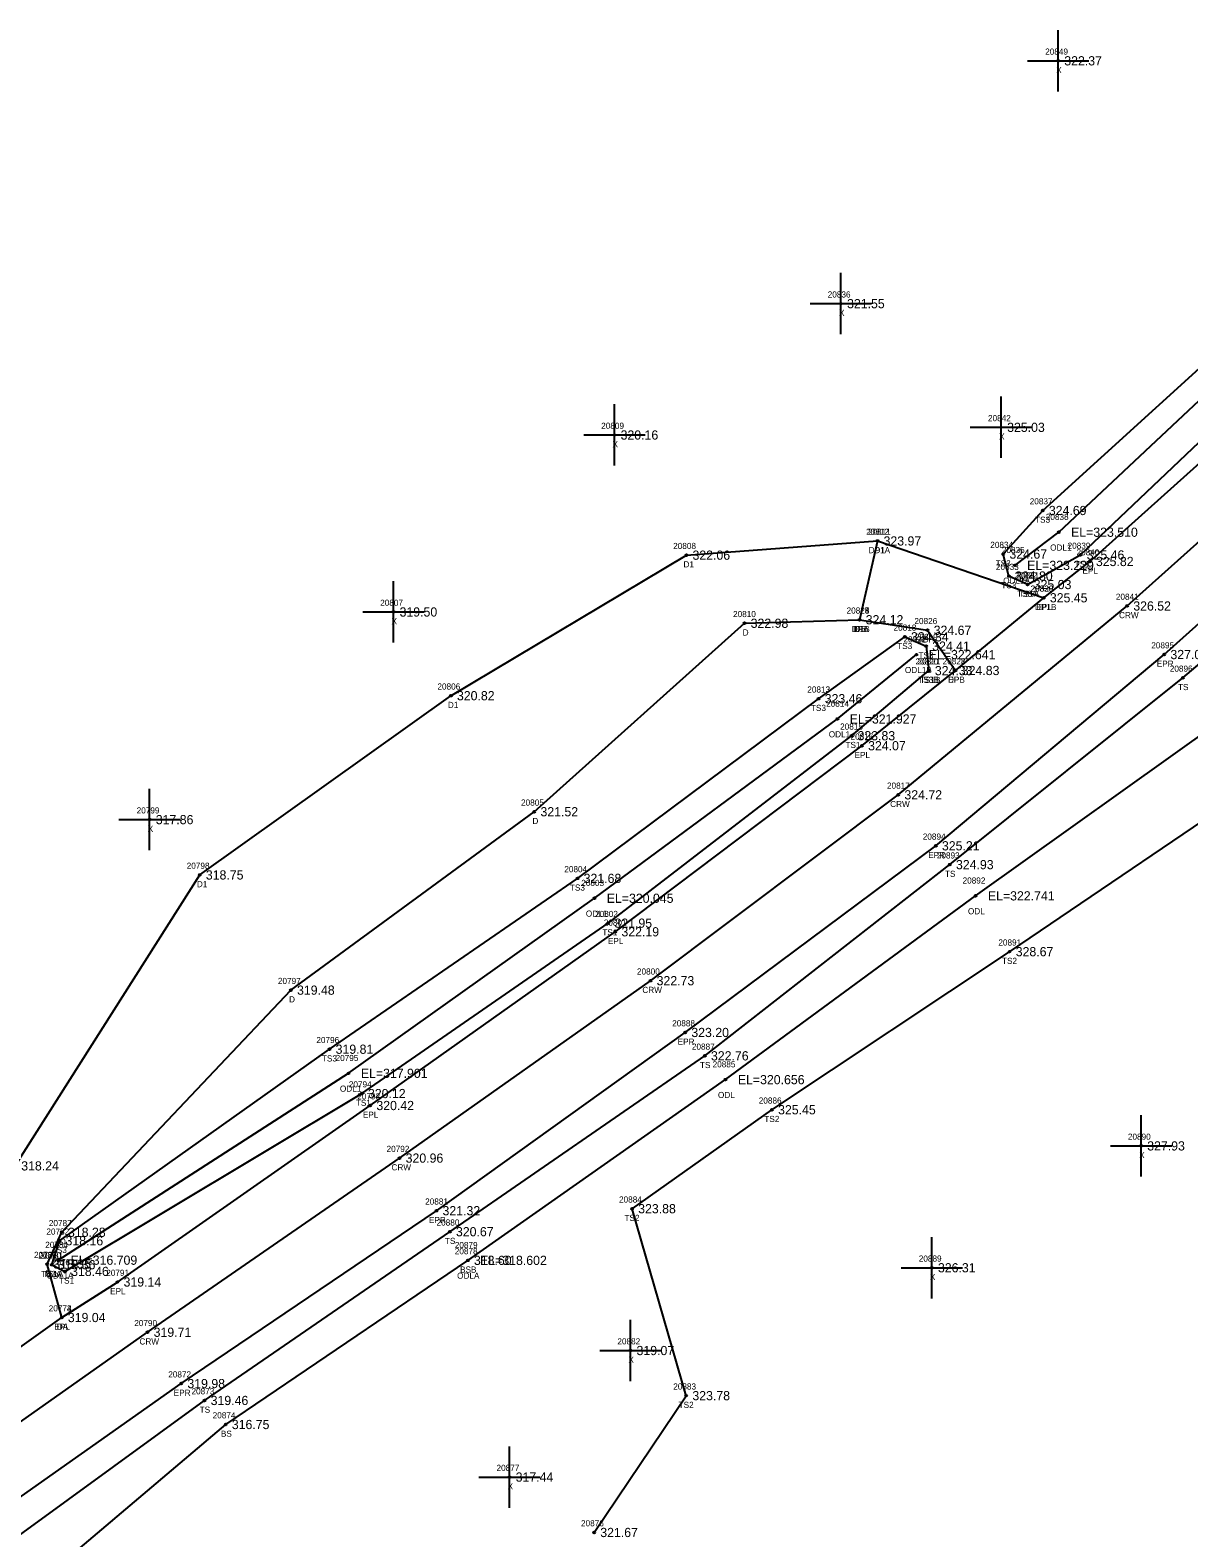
# Model space of a CAD drawing. Extents: x 1865771 to 1866867, y 910387 to 913581.
# Drawn here: x 1866485.5 to 1866674.4, y 913298.4 to 913544.2 of the extents above; entities that cross this region are included whole.
import ezdxf

# ---------------------------------------------------------------- set-up
doc = ezdxf.new("R2010")
doc.units = 0
for name, color, linetype in [('RD_DTM_BkLn1', 7, 'Continuous'), ('RD_DTM_BkLn2', 7, 'Continuous'), ('RD_DTM_BkLn_txCode', 7, 'Continuous'), ('RD_EX_Driveway', 7, 'Continuous'), ('RD_EX_Driveway_txCode', 7, 'Continuous'), ('RD_EX_H2O', 7, 'Continuous'), ('RD_EX_H2O_txCode', 7, 'Continuous'), ('RD_EX_Misc', 7, 'Continuous'), ('RD_EX_Misc_txCode', 7, 'Continuous'), ('RD_EX_Road', 7, 'Continuous'), ('RD_EX_Road_txCode', 7, 'Continuous'), ('RD_EX_TX_Driveway_ELEV', 7, 'Continuous'), ('RD_EX_TX_H2O_ELEV', 7, 'Continuous'), ('RD_EX_TX_Misc_ELEV', 7, 'Continuous'), ('RD_EX_TX_Road_ELEV', 7, 'Continuous'), ('RD_HC_Survey_ELEV', 7, 'Continuous'), ('RD_HC_Survey_txCode', 7, 'Continuous'), ('RD_SMD_Locator', 7, 'Continuous')]:
    doc.layers.add(name, color=color, linetype=linetype)

msp = doc.modelspace()

# ---------------------------------------------------------------- linework, layer by layer
at = {"layer": 'RD_DTM_BkLn1'}
msp.add_lwpolyline([(1866198.19, 913076.43), (1866231.43, 913114.18), (1866266.39, 913149.89), (1866303.96, 913183.9), (1866342.32, 913215.01), (1866422.98, 913274.26), (1866504.67, 913331.92), (1866545.74, 913360.31), (1866586.64, 913389.23), (1866627.03, 913419.53), (1866664.33, 913450.32), (1866701.01, 913483.14), (1866738.23, 913519.69)], dxfattribs=at)
at = {"layer": 'RD_DTM_BkLn2'}
for points in [[(1866648.11, 913453.81), (1866645.06, 913455.2), (1866644.14, 913458.78), (1866650.57, 913465.88), (1866688, 913499.92), (1866720.64, 913534.32)], [(1866648.11, 913453.81), (1866656.74, 913458.64), (1866693.26, 913493.4), (1866726.81, 913527.33)], [(1866443.26, 913211.06), (1866417.42, 913242.5), (1866419.02, 913252.7), (1866432.66, 913261.59), (1866513.96, 913320.8), (1866553.94, 913348.31), (1866595.5, 913376.98), (1866635.43, 913408.15), (1866673.42, 913438.6), (1866712.76, 913471.89), (1866747.8, 913506.8)], [(1866577.46, 913299.28), (1866592.47, 913321.58), (1866583.64, 913352.06), (1866606.44, 913368.19), (1866645.17, 913393.96), (1866688.43, 913423.29), (1866720.88, 913447.65), (1866761.04, 913493.25)], [(1866489.05, 913342.93), (1866490.31, 913346.83), (1866534.33, 913378.06), (1866574.75, 913405.91), (1866614.04, 913435.2), (1866628.1, 913445.29), (1866631.56, 913443.77), (1866631.99, 913439.78)], [(1866489.05, 913342.93), (1866491.22, 913341.84), (1866539.6, 913370.83), (1866579.77, 913398.61), (1866619.38, 913429.16), (1866631.99, 913439.78)], [(1866443.26, 913211.06), (1866430.21, 913243.04), (1866517.41, 913316.88), (1866556.87, 913343.64)]]:
    msp.add_lwpolyline(points, dxfattribs=at)
at = {"layer": 'RD_EX_Driveway'}
msp.add_line((1866623.63, 913460.92), (1866650.73, 913451.65), dxfattribs=at)
for points in [[(1866476.76, 913324.36), (1866477.78, 913348), (1866483.09, 913359.04), (1866513.18, 913406.47), (1866554.1, 913435.69), (1866592.49, 913458.6), (1866623.63, 913460.92), (1866620.72, 913448.07)], [(1866490.69, 913334.32), (1866488.32, 913343.03), (1866490.71, 913348.22), (1866528.04, 913387.69), (1866567.71, 913416.77), (1866601.97, 913447.5), (1866620.72, 913448.07)], [(1866620.72, 913448.07), (1866631.8, 913446.36), (1866636.38, 913439.8)]]:
    msp.add_lwpolyline(points, dxfattribs=at)
at = {"layer": 'RD_EX_H2O'}
for points in [[(1866646.03, 913456.94), (1866653.19, 913462.34), (1866690.21, 913497.06), (1866722.84, 913530.86)], [(1866556.87, 913343.64), (1866598.88, 913373.1), (1866639.63, 913403.06), (1866679.21, 913431.34), (1866717.44, 913467.83), (1866753.23, 913502.29)], [(1866490.12, 913343.67), (1866537.44, 913374.13), (1866577.52, 913402.67), (1866617.11, 913431.9), (1866629.99, 913442.38)]]:
    msp.add_lwpolyline(points, dxfattribs=at)
at = {"layer": 'RD_EX_Misc'}
for p, q in [((1866653.08, 913534.19), (1866653.08, 913544.19)), ((1866648.08, 913539.19), (1866658.08, 913539.19)), ((1866617.68, 913494.6), (1866617.68, 913504.6)), ((1866612.68, 913499.6), (1866622.68, 913499.6)), ((1866643.77, 913474.44), (1866643.77, 913484.44)), ((1866580.77, 913473.19), (1866580.77, 913483.19)), ((1866638.77, 913479.44), (1866648.77, 913479.44)), ((1866575.77, 913478.19), (1866585.77, 913478.19)), ((1866544.75, 913444.34), (1866544.75, 913454.34)), ((1866539.75, 913449.34), (1866549.75, 913449.34)), ((1866505.02, 913410.49), (1866505.02, 913420.49)), ((1866500.02, 913415.49), (1866510.02, 913415.49)), ((1866666.6, 913357.3), (1866666.6, 913367.3)), ((1866661.6, 913362.3), (1866671.6, 913362.3)), ((1866632.49, 913337.43), (1866632.49, 913347.43)), ((1866627.49, 913342.43), (1866637.49, 913342.43)), ((1866583.37, 913323.94), (1866583.37, 913333.94)), ((1866578.37, 913328.94), (1866588.37, 913328.94)), ((1866563.67, 913303.31), (1866563.67, 913313.31)), ((1866558.67, 913308.31), (1866568.67, 913308.31))]:
    msp.add_line(p, q, dxfattribs=at)
at = {"layer": 'RD_EX_Road'}
for points in [[(1866198.19, 913076.43), (1866191.03, 913082.87), (1866223.86, 913120.42), (1866228.39, 913125.33), (1866247.77, 913145.2), (1866298.81, 913191.9), (1866335.78, 913222.11), (1866414.11, 913280.06), (1866476.76, 913324.36), (1866490.69, 913334.32), (1866499.77, 913340.11), (1866540.97, 913368.88), (1866580.91, 913397.2), (1866621.11, 913427.53), (1866636.38, 913439.8), (1866650.73, 913451.65), (1866658.24, 913457.57), (1866695.23, 913490.79), (1866731.5, 913526.47)], [(1866198.19, 913076.43), (1866206.15, 913069.97), (1866239, 913107.62), (1866272.78, 913142.13), (1866310.33, 913176.03), (1866348.57, 913206.96), (1866383.21, 913233.26), (1866415.26, 913256.44), (1866428.91, 913266.25), (1866510.17, 913323.55), (1866551.75, 913351.73), (1866592.3, 913380.79), (1866633.14, 913411.22), (1866670.38, 913442.4), (1866708.09, 913476.17), (1866744.52, 913511.6)]]:
    msp.add_lwpolyline(points, dxfattribs=at)
at = {"layer": 'RD_SMD_Locator'}
for centre in [(1866653.08, 913539.19), (1866617.68, 913499.6), (1866643.77, 913479.44), (1866580.77, 913478.19), (1866650.57, 913465.88), (1866653.19, 913462.34), (1866623.63, 913460.92), (1866623.63, 913460.92), (1866592.49, 913458.6), (1866644.14, 913458.78), (1866646.03, 913456.94), (1866656.74, 913458.64), (1866658.24, 913457.57), (1866645.06, 913455.2), (1866648.11, 913453.81), (1866648.11, 913453.81), (1866650.73, 913451.65), (1866650.73, 913451.65), (1866664.33, 913450.32), (1866544.75, 913449.34), (1866601.97, 913447.5), (1866620.72, 913448.07), (1866620.72, 913448.07), (1866620.72, 913448.07), (1866628.1, 913445.29), (1866631.8, 913446.36), (1866629.99, 913442.38), (1866631.56, 913443.77), (1866670.38, 913442.4), (1866631.99, 913439.78), (1866631.99, 913439.78), (1866636.38, 913439.8), (1866636.38, 913439.8), (1866673.42, 913438.6), (1866554.1, 913435.69), (1866614.04, 913435.2), (1866617.11, 913431.9), (1866619.38, 913429.16), (1866621.11, 913427.53), (1866627.03, 913419.53), (1866505.02, 913415.49), (1866567.71, 913416.77), (1866633.14, 913411.22), (1866635.43, 913408.15), (1866513.18, 913406.47), (1866574.75, 913405.91), (1866639.63, 913403.06), (1866577.52, 913402.67), (1866579.77, 913398.61), (1866580.91, 913397.2), (1866645.17, 913393.96), (1866586.64, 913389.23), (1866528.04, 913387.69), (1866592.3, 913380.79), (1866534.33, 913378.06), (1866595.5, 913376.98), (1866537.44, 913374.13), (1866539.6, 913370.83), (1866598.88, 913373.1), (1866540.97, 913368.88), (1866606.44, 913368.19), (1866666.6, 913362.3), (1866545.74, 913360.31), (1866551.75, 913351.73), (1866583.64, 913352.06), (1866490.31, 913346.83), (1866490.71, 913348.22), (1866553.94, 913348.31), (1866488.32, 913343.03), (1866489.05, 913342.93), (1866489.05, 913342.93), (1866490.12, 913343.67), (1866491.22, 913341.84), (1866556.87, 913343.64), (1866556.87, 913343.64), (1866632.49, 913342.43), (1866499.77, 913340.11), (1866490.69, 913334.32), (1866490.69, 913334.32), (1866504.67, 913331.92), (1866583.37, 913328.94), (1866510.17, 913323.55), (1866513.96, 913320.8), (1866592.47, 913321.58), (1866517.41, 913316.88), (1866563.67, 913308.31), (1866577.46, 913299.28)]:
    msp.add_circle(centre, 0.15, dxfattribs=at)

# ---------------------------------------------------------------- texts
at = {"layer": 'RD_DTM_BkLn_txCode'}
for s, p in [('20837', (1866648.45, 913466.88)), ('TS3', (1866649.32, 913463.88)), ('20834', (1866642.02, 913459.78)), ('20839', (1866654.62, 913459.64)), ('TS3', (1866642.9, 913456.78)), ('20833', (1866642.94, 913456.2)), ('TS1', (1866655.78, 913456.64)), ('20832', (1866645.99, 913454.81)), ('20831', (1866646.28, 913454.81)), ('TS3', (1866643.82, 913453.2)), ('TS3A', (1866646.38, 913451.81)), ('TS1A', (1866646.66, 913451.81)), ('20818', (1866626.26, 913446.29)), ('20819', (1866629.73, 913444.77)), ('TS3', (1866626.85, 913443.29)), ('TS3', (1866630.32, 913441.77)), ('20820', (1866629.84, 913440.78)), ('20821', (1866630.16, 913440.78)), ('20896', (1866671.28, 913439.6)), ('TS3B', (1866630.28, 913437.78)), ('TS1B', (1866630.56, 913437.78)), ('TS', (1866672.62, 913436.6)), ('20813', (1866612.2, 913436.2)), ('TS3', (1866612.79, 913433.2)), ('20815', (1866617.55, 913430.16)), ('TS1', (1866618.42, 913427.16)), ('20804', (1866572.6, 913406.91)), ('20893', (1866633.31, 913409.15)), ('TS', (1866634.64, 913406.15)), ('TS3', (1866573.51, 913403.91)), ('20802', (1866577.61, 913399.61)), ('TS1', (1866578.8, 913396.61)), ('20891', (1866643.34, 913394.96)), ('TS2', (1866643.93, 913391.96)), ('20796', (1866532.19, 913379.06)), ('20887', (1866593.39, 913377.98)), ('TS3', (1866533.09, 913376.06)), ('TS', (1866594.71, 913374.98)), ('20794', (1866537.48, 913371.83)), ('TS1', (1866538.63, 913368.83)), ('20886', (1866604.29, 913369.19)), ('TS2', (1866605.19, 913366.19)), ('20884', (1866581.52, 913353.06)), ('20782', (1866488.19, 913347.83)), ('20880', (1866551.78, 913349.31)), ('TS2', (1866582.4, 913350.06)), ('TS', (1866553.14, 913346.31)), ('20780', (1866486.89, 913343.93)), ('20781', (1866487.21, 913343.93)), ('TS3', (1866489.07, 913344.83)), ('20878', (1866554.75, 913344.64)), ('TS3A', (1866487.32, 913340.93)), ('TS1A', (1866487.6, 913340.93)), ('20783', (1866489.1, 913342.84)), ('BSB', (1866555.61, 913341.64)), ('TS1', (1866490.26, 913339.84)), ('20873', (1866511.84, 913321.8)), ('20883', (1866590.35, 913322.58)), ('TS', (1866513.17, 913318.8)), ('TS2', (1866591.23, 913319.58)), ('20874', (1866515.29, 913317.88)), ('BS', (1866516.63, 913314.88)), ('20876', (1866575.32, 913300.28))]:
    msp.add_text(s, height=1, dxfattribs=at).set_placement(p)
at = {"layer": 'RD_EX_Driveway_txCode'}
for s, p in [('20812', (1866621.79, 913461.92)), ('20811', (1866622.08, 913461.92)), ('20808', (1866590.34, 913459.6)), ('DP1A', (1866622.2, 913458.92)), ('D1', (1866623.16, 913458.92)), ('D1', (1866592.02, 913456.6)), ('20829', (1866648.61, 913452.65)), ('20823', (1866618.6, 913449.07)), ('20824', (1866618.6, 913449.07)), ('20825', (1866618.6, 913449.07)), ('DP1B', (1866649.31, 913449.65)), ('20810', (1866600.1, 913448.5)), ('20826', (1866629.66, 913447.36)), ('D', (1866601.67, 913445.5)), ('DPA', (1866619.45, 913446.07)), ('D1B', (1866619.78, 913446.07)), ('DB', (1866619.94, 913446.07)), ('DP', (1866631.02, 913444.36)), ('20827', (1866634.26, 913440.8)), ('20806', (1866551.92, 913436.69)), ('DPB', (1866635.13, 913437.8)), ('D1', (1866553.62, 913433.69)), ('20805', (1866565.55, 913417.77)), ('D', (1866567.4, 913414.77)), ('20798', (1866511.06, 913407.47)), ('D1', (1866512.71, 913404.47)), ('20797', (1866525.92, 913388.69)), ('D', (1866527.74, 913385.69)), ('20787', (1866488.59, 913349.22)), ('D', (1866490.4, 913346.22)), ('20786', (1866486.18, 913344.03)), ('D', (1866488.02, 913341.03)), ('20774', (1866488.57, 913335.32)), ('DA', (1866489.89, 913332.32))]:
    msp.add_text(s, height=1, dxfattribs=at).set_placement(p)
at = {"layer": 'RD_EX_H2O_txCode'}
for s, p in [('20838', (1866651.07, 913464.34)), ('20835', (1866643.91, 913458.94)), ('ODL1', (1866651.78, 913459.34)), ('ODL1A', (1866644.13, 913453.94)), ('20822', (1866627.87, 913444.38)), ('ODL1B', (1866628.11, 913439.38)), ('20814', (1866615.27, 913433.9)), ('ODL1', (1866615.7, 913428.9)), ('20803', (1866575.36, 913404.67)), ('20892', (1866637.51, 913405.06)), ('ODL1', (1866576.11, 913399.67)), ('ODL', (1866638.38, 913400.06)), ('20795', (1866535.32, 913376.13)), ('20885', (1866596.77, 913375.1)), ('ODL1', (1866536.03, 913371.13)), ('ODL', (1866597.64, 913370.1)), ('20784', (1866488, 913345.67)), ('20879', (1866554.75, 913345.64)), ('ODL1A', (1866488.22, 913340.67)), ('ODLA', (1866555.13, 913340.64))]:
    msp.add_text(s, height=1, dxfattribs=at).set_placement(p)
at = {"layer": 'RD_EX_Misc_txCode'}
for s, p in [('20849', (1866650.97, 913540.19)), ('X', (1866652.77, 913537.19)), ('20836', (1866615.53, 913500.6)), ('X', (1866617.36, 913497.6)), ('20809', (1866578.61, 913479.19)), ('20842', (1866641.65, 913480.44)), ('X', (1866580.45, 913476.19)), ('X', (1866643.46, 913477.44)), ('20807', (1866542.59, 913450.34)), ('X', (1866544.44, 913447.34)), ('20799', (1866502.9, 913416.49)), ('X', (1866504.7, 913413.49)), ('20890', (1866664.45, 913363.3)), ('X', (1866666.29, 913360.3)), ('20889', (1866630.37, 913343.43)), ('X', (1866632.18, 913340.43)), ('20882', (1866581.25, 913329.94)), ('X', (1866583.05, 913326.94)), ('20877', (1866561.55, 913309.31)), ('X', (1866563.36, 913306.31))]:
    msp.add_text(s, height=1, dxfattribs=at).set_placement(p)
at = {"layer": 'RD_EX_Road_txCode'}
for s, p in [('20840', (1866656.08, 913458.57)), ('EPL', (1866657.04, 913455.57)), ('20830', (1866648.57, 913452.65)), ('EPL', (1866649.52, 913449.65)), ('20895', (1866668.26, 913443.4)), ('20828', (1866634.26, 913440.8)), ('EPR', (1866669.15, 913440.4)), ('EPL', (1866635.18, 913437.8)), ('20816', (1866619.25, 913428.53)), ('EPL', (1866619.9, 913425.53)), ('20894', (1866631.02, 913412.22)), ('EPR', (1866631.91, 913409.22)), ('20801', (1866579.03, 913398.2)), ('EPL', (1866579.7, 913395.2)), ('20888', (1866590.18, 913381.79)), ('EPR', (1866591.07, 913378.79)), ('20793', (1866538.86, 913369.88)), ('EPL', (1866539.77, 913366.88)), ('20881', (1866549.92, 913352.73)), ('EPR', (1866550.53, 913349.73)), ('20791', (1866497.94, 913341.11)), ('EPL', (1866498.57, 913338.11)), ('20773', (1866488.57, 913335.32)), ('EPL', (1866489.48, 913332.32)), ('20872', (1866508.05, 913324.55)), ('EPR', (1866508.94, 913321.55))]:
    msp.add_text(s, height=1, dxfattribs=at).set_placement(p)
at = {"layer": 'RD_EX_TX_Driveway_ELEV'}
for s, p in [('323.97', (1866624.63, 913460.17)), ('323.97', (1866624.63, 913460.17)), ('322.06', (1866593.49, 913457.85)), ('325.45', (1866651.73, 913450.9)), ('322.98', (1866602.97, 913446.75)), ('324.12', (1866621.72, 913447.32)), ('324.12', (1866621.72, 913447.32)), ('324.12', (1866621.72, 913447.32)), ('324.67', (1866632.8, 913445.61)), ('324.83', (1866637.38, 913439.05)), ('320.82', (1866555.1, 913434.94)), ('321.52', (1866568.71, 913416.02)), ('318.75', (1866514.18, 913405.72)), ('319.48', (1866529.04, 913386.94)), ('318.24', (1866484.09, 913358.29)), ('318.28', (1866491.71, 913347.47)), ('318.35', (1866489.32, 913342.28)), ('319.04', (1866491.69, 913333.57))]:
    msp.add_text(s, height=1.5, dxfattribs=at).set_placement(p)
at = {"layer": 'RD_EX_TX_H2O_ELEV'}
for s, p in [('EL=323.510', (1866655.19, 913461.59)), ('EL=323.229', (1866648.03, 913456.19)), ('EL=322.641', (1866631.99, 913441.63)), ('EL=321.927', (1866619.11, 913431.15)), ('EL=320.045', (1866579.52, 913401.92)), ('EL=322.741', (1866641.63, 913402.31)), ('EL=317.901', (1866539.44, 913373.38)), ('EL=320.656', (1866600.88, 913372.35)), ('EL=316.709', (1866492.12, 913342.92)), ('EL=318.602', (1866558.87, 913342.89))]:
    msp.add_text(s, height=1.5, dxfattribs=at).set_placement(p)
at = {"layer": 'RD_EX_TX_Misc_ELEV'}
for s, p in [('322.37', (1866654.08, 913538.44)), ('321.55', (1866618.68, 913498.85)), ('325.03', (1866644.77, 913478.69)), ('320.16', (1866581.77, 913477.44)), ('324.69', (1866651.57, 913465.13)), ('324.67', (1866645.14, 913458.03)), ('325.46', (1866657.74, 913457.89)), ('324.80', (1866646.06, 913454.45)), ('325.03', (1866649.11, 913453.06)), ('325.03', (1866649.11, 913453.06)), ('319.50', (1866545.75, 913448.59)), ('324.34', (1866629.1, 913444.54)), ('324.41', (1866632.56, 913443.02)), ('324.33', (1866632.99, 913439.03)), ('324.33', (1866632.99, 913439.03)), ('323.46', (1866615.04, 913434.45)), ('323.83', (1866620.38, 913428.41)), ('317.86', (1866506.02, 913414.74)), ('324.93', (1866636.43, 913407.4)), ('321.68', (1866575.75, 913405.16)), ('321.95', (1866580.77, 913397.86)), ('328.67', (1866646.17, 913393.21)), ('319.81', (1866535.33, 913377.31)), ('322.76', (1866596.5, 913376.23)), ('320.12', (1866540.6, 913370.08)), ('325.45', (1866607.44, 913367.44)), ('327.93', (1866667.6, 913361.55)), ('323.88', (1866584.64, 913351.31)), ('320.67', (1866554.94, 913347.56)), ('318.16', (1866491.31, 913346.08)), ('318.60', (1866557.87, 913342.89)), ('318.36', (1866490.05, 913342.18)), ('318.36', (1866490.05, 913342.18)), ('318.46', (1866492.22, 913341.09)), ('326.31', (1866633.49, 913341.68)), ('319.07', (1866584.37, 913328.19)), ('323.78', (1866593.47, 913320.83)), ('319.46', (1866514.96, 913320.05)), ('316.75', (1866518.41, 913316.13)), ('317.44', (1866564.67, 913307.56)), ('321.67', (1866578.46, 913298.53))]:
    msp.add_text(s, height=1.5, dxfattribs=at).set_placement(p)
at = {"layer": 'RD_EX_TX_Road_ELEV'}
for s, p in [('325.82', (1866659.24, 913456.82)), ('325.45', (1866651.73, 913450.9)), ('327.04', (1866671.38, 913441.65)), ('324.83', (1866637.38, 913439.05)), ('324.07', (1866622.11, 913426.78)), ('325.21', (1866634.14, 913410.47)), ('322.19', (1866581.91, 913396.45)), ('323.20', (1866593.3, 913380.04)), ('320.42', (1866541.97, 913368.13)), ('321.32', (1866552.75, 913350.98)), ('319.14', (1866500.77, 913339.36)), ('319.04', (1866491.69, 913333.57)), ('319.98', (1866511.17, 913322.8))]:
    msp.add_text(s, height=1.5, dxfattribs=at).set_placement(p)
at = {"layer": 'RD_HC_Survey_ELEV'}
for s, p in [('326.52', (1866665.33, 913449.57)), ('324.72', (1866628.03, 913418.78)), ('322.73', (1866587.64, 913388.48)), ('320.96', (1866546.74, 913359.56)), ('319.71', (1866505.67, 913331.17))]:
    msp.add_text(s, height=1.5, dxfattribs=at).set_placement(p)
at = {"layer": 'RD_HC_Survey_txCode'}
for s, p in [('20841', (1866662.49, 913451.32)), ('CRW', (1866663.01, 913448.32)), ('20817', (1866625.19, 913420.53)), ('CRW', (1866625.71, 913417.53)), ('20800', (1866584.44, 913390.23)), ('CRW', (1866585.32, 913387.23)), ('20792', (1866543.63, 913361.31)), ('CRW', (1866544.43, 913358.31)), ('20790', (1866502.51, 913332.92)), ('CRW', (1866503.36, 913329.92))]:
    msp.add_text(s, height=1, dxfattribs=at).set_placement(p)

doc.saveas('drawing.dxf')
